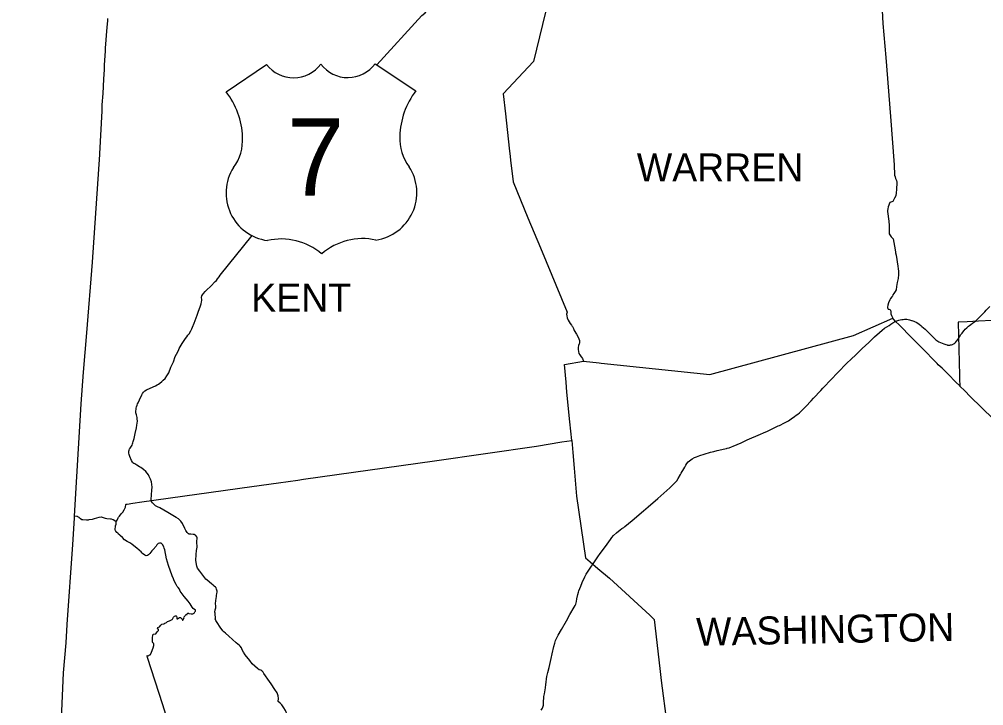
# Model space of a CAD drawing. Extents: x 0 to 2603, y -226 to 830.
# Drawn here: x 54.18 to 100.65, y 607.68 to 640.75 of the extents above; entities that cross this region are included whole.
import ezdxf

# ---------------------------------------------------------------- set-up
doc = ezdxf.new("R2010")
doc.units = 0
for name, color, linetype in [('CT_TSH_Map_Town_Limits', 7, 'Continuous'), ('CT_TSH_Map_Town_Text', 7, 'Continuous'), ('CT_TSH_Map_US_and_State_Routes', 7, 'Continuous')]:
    doc.layers.add(name, color=color, linetype=linetype)

msp = doc.modelspace()

# ---------------------------------------------------------------- linework, layer by layer
at = {"layer": 'CT_TSH_Map_Town_Limits'}
for points in [[(80.1, 643.411), (79.534, 641.088), (78.955, 638.71), (77.491, 637.157), (77.606, 636.187)], [(95.751, 641.169), (95.796, 640.551), (95.937, 638.907), (96.162, 636.059), (96.342, 633.743), (96.355, 633.241), (96.377, 633.159), (96.402, 633.086), (96.443, 632.986), (96.463, 632.909), (96.46, 632.887), (96.444, 632.554), (96.427, 632.388), (96.408, 632.247), (96.352, 632.129), (96.27, 631.97), (96.12, 631.921), (96.054, 631.705), (96.036, 631.609), (96.014, 631.534), (96.019, 631.485), (96.077, 631.022), (96.096, 630.809), (96.095, 630.53), (96.102, 630.489), (96.099, 630.416), (96.192, 630.266), (96.284, 630.179), (96.344, 629.81), (96.397, 629.545), (96.398, 629.494), (96.424, 629.385), (96.508, 628.847), (96.532, 628.726), (96.545, 628.614), (96.54, 628.459), (96.52, 628.263), (96.479, 628.072), (96.455, 627.868), (96.429, 627.708), (96.384, 627.626), (96.327, 627.532), (96.279, 627.466), (96.253, 627.403), (96.218, 627.372), (96.162, 627.297), (96.125, 627.234), (96.069, 627.092), (96.03, 626.969), (96.014, 626.875), (96.015, 626.842), (96.049, 626.79), (96.085, 626.782), (96.126, 626.76), (96.154, 626.734), (96.176, 626.655), (96.17, 626.609), (96.179, 626.557), (96.212, 626.47), (96.236, 626.419), (96.264, 626.347)], [(58.436, 640.783), (58.423, 640.667), (58.404, 640.363), (58.322, 639.354), (58.318, 639.232), (58.276, 638.538), (58.267, 638.336), (58.236, 637.859), (58.2, 637.17), (58.164, 636.633), (58.158, 636.346), (58.04, 634.269), (58.049, 634.232), (57.685, 629.053), (57.412, 625.648), (57.26, 623.755), (57.139, 622.216), (56.889, 617.899), (56.827, 616.808)], [(77.606, 636.187), (77.791, 634.532), (77.837, 634.146), (77.851, 633.965), (77.97, 632.916), (78.687, 631.189), (79.299, 629.735), (80.584, 626.632), (80.56, 626.594), (80.552, 626.544), (80.558, 626.464), (80.578, 626.369), (80.626, 626.253), (80.731, 626.091), (80.79, 626.019), (80.808, 625.983), (80.832, 625.948), (80.881, 625.85), (80.923, 625.757), (81.035, 625.586), (81.096, 625.47), (81.145, 625.352), (81.168, 625.279), (81.172, 625.143), (81.165, 625.107), (81.129, 625.026), (81.105, 624.943), (81.109, 624.835), (81.119, 624.745), (81.147, 624.65), (81.185, 624.575), (81.256, 624.49), (81.276, 624.472), (81.322, 624.399), (81.372, 624.278)], [(123.082, 617.737), (122.957, 618.259), (121.992, 621.988), (120.401, 627.917), (118.766, 627.682), (117.516, 627.46), (112.802, 626.95), (109.976, 626.777), (106.508, 626.575), (104.157, 626.438), (104.117, 626.429), (103.372, 626.362), (103.176, 626.354), (101.954, 626.288), (101.061, 626.24), (100.398, 626.21), (99.854, 626.177), (99.416, 626.152), (99.483, 623.59), (99.489, 623.377), (99.497, 623.12), (99.5, 623.08)], [(81.372, 624.278), (82.128, 624.19), (82.219, 624.187), (87.456, 623.636), (94.378, 625.507), (96.264, 626.347)], [(99.5, 623.08), (99.48, 623.098), (99.325, 623.256), (98.917, 623.661), (98.772, 623.812), (98.643, 623.94), (98.463, 624.106), (98.404, 624.168), (98.212, 624.358), (97.842, 624.742), (97.208, 625.387), (96.558, 626.046), (96.422, 626.178), (96.319, 626.285), (96.264, 626.347)], [(80.796, 620.456), (80.701, 621.352), (80.566, 622.789), (80.534, 623.262), (80.458, 624.12), (81.372, 624.278)], [(101.957, 615.974), (102.069, 617.732), (102.222, 620.412), (100.003, 622.578), (99.738, 622.841), (99.5, 623.08)], [(58.848, 616.535), (58.859, 616.562), (58.891, 616.62), (58.943, 616.728), (58.961, 616.758), (59.012, 616.816), (59.086, 616.918), (59.165, 617.009), (59.227, 617.111), (59.276, 617.212), (59.294, 617.242), (59.319, 617.368), (59.329, 617.382), (59.372, 617.393), (59.654, 617.437), (60.092, 617.494), (65.379, 618.237), (66.663, 618.413), (67.598, 618.548), (67.871, 618.585), (74.191, 619.469), (79.094, 620.179), (80.33, 620.389), (80.796, 620.456)], [(80.796, 620.456), (80.848, 619.874), (80.911, 619.122), (80.967, 618.543), (81.013, 617.971), (81.031, 617.779), (81.465, 614.798), (81.68, 614.608), (82.055, 614.284), (82.614, 613.822), (84.555, 612.035), (84.765, 611.835), (85.042, 609.477), (85.111, 608.892), (85.384, 606.809), (85.491, 606.099), (85.7, 604.798), (85.811, 603.998), (86.203, 601.565), (86.464, 600.083), (86.508, 599.804)], [(56.827, 616.808), (56.825, 616.707), (56.751, 615.439), (56.478, 611.587), (56.42, 610.703), (56.299, 609.259), (56.195, 607.042), (56.149, 605.817), (56.136, 605.715), (56.079, 605.082), (55.938, 603.558), (55.794, 601.866), (55.531, 598.701), (55.425, 597.346), (55.216, 594.938), (55.115, 593.729), (54.937, 591.45), (54.867, 590.481), (54.787, 589.52), (54.68, 588.216), (54.554, 586.636), (54.317, 583.992), (54.288, 583.676), (54.18, 582.466)], [(58.848, 616.535), (58.778, 616.589), (58.707, 616.625), (58.621, 616.66), (58.581, 616.665), (58.401, 616.675), (58.333, 616.691), (58.193, 616.747), (58.148, 616.753), (58.124, 616.755), (58.013, 616.745), (57.788, 616.68), (57.684, 616.648), (57.537, 616.634), (57.491, 616.623), (57.414, 616.618), (57.248, 616.628), (57.194, 616.637), (57.129, 616.675), (57.089, 616.713), (57.061, 616.739), (57.004, 616.778), (56.987, 616.791), (56.946, 616.8), (56.827, 616.808)], [(62.663, 612.228), (62.671, 612.274), (62.563, 612.365), (62.504, 612.424), (62.418, 612.58), (62.317, 612.715), (62.124, 612.941), (61.932, 613.196), (61.904, 613.291), (61.837, 613.374), (61.788, 613.425), (61.731, 613.516), (61.643, 613.691), (61.606, 613.791), (61.54, 613.929), (61.363, 614.425), (61.28, 614.757), (61.194, 615.191), (61.168, 615.273), (61.141, 615.336), (61.079, 615.437), (61.046, 615.478), (61.009, 615.51), (60.982, 615.515), (60.935, 615.509), (60.868, 615.488), (60.812, 615.429), (60.768, 615.363), (60.634, 615.197), (60.573, 615.134), (60.463, 615.007), (60.406, 614.948), (60.363, 614.913), (60.293, 614.906), (60.23, 614.927), (60.11, 615.016), (60.072, 615.048), (60.063, 615.075), (59.847, 615.265), (59.783, 615.313), (59.595, 615.467), (59.506, 615.525), (59.384, 615.588), (59.255, 615.672), (59.149, 615.776), (59.053, 615.857), (59.025, 615.896), (58.946, 615.965), (58.923, 615.988), (58.882, 616.018), (58.832, 616.082), (58.817, 616.107), (58.8, 616.169), (58.8, 616.197), (58.817, 616.3), (58.823, 616.35), (58.842, 616.43), (58.848, 616.535)], [(61.316, 606.997), (61.09, 607.721), (60.358, 609.995), (60.338, 610.081), (60.341, 610.093), (60.417, 610.079), (60.422, 610.089), (60.459, 610.121), (60.484, 610.128), (60.503, 610.141), (60.523, 610.174), (60.545, 610.262), (60.634, 610.471), (60.659, 610.585), (60.666, 610.66), (60.647, 610.686), (60.613, 610.709), (60.597, 610.734), (60.6, 610.936), (60.616, 611.085), (60.634, 611.112), (60.651, 611.12), (60.756, 611.146), (60.83, 611.231), (60.884, 611.306), (60.888, 611.351), (60.847, 611.421), (60.862, 611.447), (60.941, 611.483), (61.003, 611.564), (61.051, 611.609), (61.141, 611.629), (61.196, 611.647), (61.271, 611.686), (61.324, 611.733), (61.41, 611.759), (61.54, 611.826), (61.564, 611.852), (61.61, 611.94), (61.66, 611.991), (61.711, 612.008), (61.736, 612), (61.752, 611.984), (61.768, 611.934), (61.768, 611.888), (61.773, 611.866), (61.791, 611.859), (61.809, 611.87), (61.845, 611.902), (61.898, 611.919), (61.941, 611.924), (61.996, 611.886), (62.019, 611.877), (62.033, 611.851), (62.048, 611.804), (62.058, 611.8), (62.066, 611.804), (62.12, 611.904), (62.116, 611.949), (62.119, 611.966), (62.15, 611.99), (62.17, 612.025), (62.213, 612.071), (62.256, 612.069), (62.272, 612.077), (62.285, 612.128), (62.303, 612.134), (62.335, 612.128), (62.348, 612.122), (62.465, 612.098), (62.51, 612.097), (62.537, 612.104), (62.603, 612.141), (62.632, 612.201), (62.663, 612.228)]]:
    msp.add_lwpolyline(points, dxfattribs=at)
at = {"layer": 'CT_TSH_Map_US_and_State_Routes'}
for p, q in [((64.143, 637.259), (66.096, 638.575)), ((71.329, 638.606), (73.292, 637.301)), ((64.143, 637.261), (64.143, 637.259)), ((96.088, 626), (96.174, 626.06)), ((100.033, 626.049), (100.116, 626.102)), ((98.562, 625.184), (98.729, 625.115)), ((94.693, 624.786), (94.797, 624.884)), ((94.046, 624.169), (94.279, 624.388)), ((92.903, 622.979), (92.963, 623.042)), ((91.689, 621.727), (91.767, 621.795)), ((91.368, 621.501), (91.534, 621.614)), ((91.534, 621.614), (91.61, 621.67)), ((91.61, 621.67), (91.689, 621.727)), ((89.788, 620.712), (90.146, 620.869)), ((90.146, 620.869), (90.199, 620.895)), ((87.646, 619.931), (87.799, 619.969)), ((87.799, 619.969), (88.183, 620.053)), ((88.183, 620.053), (88.257, 620.073)), ((88.257, 620.073), (88.283, 620.079)), ((88.283, 620.079), (88.383, 620.106)), ((88.383, 620.106), (88.501, 620.155)), ((88.501, 620.155), (88.575, 620.185)), ((86.203, 619.083), (86.245, 619.164)), ((85.523, 618.168), (85.859, 618.516)), ((83.36, 616.318), (83.707, 616.599)), ((82.659, 615.678), (82.697, 615.736)), ((82.697, 615.736), (82.739, 615.789)), ((82.739, 615.789), (82.815, 615.873)), ((82.171, 615.015), (82.423, 615.352)), ((82.423, 615.352), (82.659, 615.678)), ((82.058, 614.851), (82.171, 615.015)), ((81.304, 613.614), (81.428, 613.879)), ((81.149, 613.214), (81.232, 613.438)), ((81.232, 613.438), (81.304, 613.614)), ((80.715, 612.064), (80.922, 612.419)), ((79.937, 610.528), (79.98, 610.691)), ((79.555, 608.702), (79.566, 608.815))]:
    msp.add_line(p, q, dxfattribs=at)
for points in [[(71.406, 638.555), (73.584, 640.927), (73.638, 640.982), (73.741, 641.068), (73.806, 641.133), (73.875, 641.199), (73.94, 641.25), (74.064, 641.329)], [(62.604, 626.11), (62.748, 626.489), (62.799, 626.642), (62.907, 626.938), (62.945, 627.044), (62.964, 627.128), (62.976, 627.201), (62.976, 627.252), (62.967, 627.342), (62.975, 627.42), (63, 627.475), (63.06, 627.544), (63.139, 627.626), (63.208, 627.695), (63.403, 627.889), (63.619, 628.111), (63.677, 628.17), (63.734, 628.239), (63.809, 628.347), (63.856, 628.414), (65.394, 630.324)], [(100.483, 626.433), (100.7, 626.655), (100.768, 626.727), (100.952, 626.916)], [(100.116, 626.102), (100.249, 626.208), (100.357, 626.303), (100.483, 626.433)], [(62.529, 625.913), (62.604, 626.11)], [(95.254, 625.318), (95.39, 625.448), (95.633, 625.658), (95.76, 625.772), (95.87, 625.867), (96.088, 626)], [(96.174, 626.06), (96.267, 626.124), (96.413, 626.197), (96.511, 626.232), (96.553, 626.245)], [(96.553, 626.245), (96.621, 626.263), (96.701, 626.279), (96.767, 626.291), (96.835, 626.3), (96.895, 626.305)], [(96.895, 626.305), (96.915, 626.308), (96.944, 626.302)], [(96.944, 626.302), (97.012, 626.288), (97.072, 626.272), (97.165, 626.244), (97.18, 626.239)], [(97.18, 626.239), (97.236, 626.219), (97.282, 626.202), (97.347, 626.175), (97.39, 626.151)], [(97.39, 626.151), (97.42, 626.138), (97.535, 626.057), (97.623, 625.992), (97.675, 625.954), (97.75, 625.885)], [(99.831, 625.886), (99.888, 625.938), (99.924, 625.971), (99.963, 626.003), (100.033, 626.049)], [(62.033, 625.128), (62.095, 625.223), (62.186, 625.369), (62.252, 625.456), (62.308, 625.528), (62.363, 625.601), (62.447, 625.736)], [(62.447, 625.736), (62.498, 625.839), (62.529, 625.913)], [(97.75, 625.885), (97.822, 625.822), (98.049, 625.599), (98.153, 625.492), (98.285, 625.366), (98.345, 625.308), (98.399, 625.265), (98.489, 625.213), (98.562, 625.184)], [(99.177, 625.099), (99.201, 625.108), (99.235, 625.135), (99.283, 625.178), (99.345, 625.245), (99.413, 625.333), (99.454, 625.393), (99.49, 625.456), (99.555, 625.557), (99.604, 625.624), (99.645, 625.677), (99.715, 625.761), (99.764, 625.816), (99.831, 625.886)], [(61.929, 624.964), (62.033, 625.128)], [(94.797, 624.884), (95.11, 625.181), (95.254, 625.318)], [(98.729, 625.115), (98.771, 625.092), (98.829, 625.074), (98.884, 625.059), (98.909, 625.056), (98.944, 625.051), (99.013, 625.056), (99.052, 625.061)], [(99.052, 625.061), (99.096, 625.069), (99.139, 625.081), (99.177, 625.099)], [(61.049, 623.291), (61.115, 623.357), (61.202, 623.45), (61.295, 623.568), (61.379, 623.718), (61.48, 623.981), (61.534, 624.085), (61.604, 624.253), (61.695, 624.501), (61.759, 624.621), (61.854, 624.791), (61.889, 624.886), (61.929, 624.964)], [(94.279, 624.388), (94.47, 624.572), (94.564, 624.664), (94.693, 624.786)], [(93.526, 623.629), (93.768, 623.881), (93.909, 624.03), (94.046, 624.169)], [(92.963, 623.042), (93.266, 623.358), (93.377, 623.477), (93.526, 623.629)], [(60.74, 623.09), (60.823, 623.129), (60.892, 623.166), (60.951, 623.211), (61.049, 623.291)], [(60.091, 622.654), (60.124, 622.724), (60.173, 622.791), (60.23, 622.85), (60.308, 622.901), (60.481, 622.977), (60.74, 623.09)], [(92.45, 622.488), (92.806, 622.87), (92.903, 622.979)], [(59.801, 621.853), (59.801, 621.887), (59.804, 621.952), (59.814, 622.019), (59.829, 622.079), (59.852, 622.154), (59.878, 622.214), (59.905, 622.272)], [(59.905, 622.272), (59.971, 622.41)], [(59.971, 622.41), (60.091, 622.654)], [(91.767, 621.795), (91.896, 621.913), (92.078, 622.097), (92.342, 622.366), (92.45, 622.488)], [(59.823, 621.069), (59.847, 621.197), (59.859, 621.292), (59.868, 621.384), (59.862, 621.493), (59.852, 621.563), (59.821, 621.69), (59.811, 621.736), (59.803, 621.792), (59.801, 621.853)], [(90.622, 621.103), (90.749, 621.154), (90.81, 621.179), (91.059, 621.307)], [(91.059, 621.307), (91.236, 621.403), (91.368, 621.501)], [(59.765, 620.785), (59.823, 621.069)], [(90.199, 620.895), (90.461, 621.023), (90.622, 621.103)], [(59.505, 619.677), (59.485, 619.727), (59.468, 619.786), (59.46, 619.841), (59.459, 619.894), (59.466, 619.945), (59.477, 619.996), (59.498, 620.048), (59.525, 620.089), (59.555, 620.131), (59.584, 620.177), (59.611, 620.226), (59.636, 620.287), (59.651, 620.34), (59.672, 620.414), (59.708, 620.547), (59.748, 620.717), (59.765, 620.785)], [(88.575, 620.185), (88.957, 620.342), (89.089, 620.406), (89.247, 620.485), (89.363, 620.542), (89.788, 620.712)], [(86.535, 619.529), (86.604, 619.576), (86.71, 619.633), (86.814, 619.672), (86.967, 619.725), (87.186, 619.801), (87.479, 619.885), (87.646, 619.931)], [(60.578, 618.203), (60.569, 618.34), (60.546, 618.463), (60.502, 618.592), (60.446, 618.717), (60.404, 618.795), (60.345, 618.879), (60.27, 618.965), (60.168, 619.061), (60.041, 619.152), (59.977, 619.193), (59.846, 619.271), (59.74, 619.326), (59.696, 619.345), (59.654, 619.373), (59.627, 619.407), (59.591, 619.49), (59.505, 619.677)], [(86.417, 619.42), (86.478, 619.48), (86.535, 619.529)], [(85.859, 618.516), (85.921, 618.626), (86.044, 618.813), (86.079, 618.876), (86.203, 619.083)], [(86.245, 619.164), (86.304, 619.261), (86.352, 619.34), (86.417, 619.42)], [(62.33, 615.966), (62.265, 616.028), (62.21, 616.112), (62.152, 616.219), (62.048, 616.462), (61.961, 616.569), (61.857, 616.673), (61.731, 616.751), (61.34, 616.985), (60.959, 617.207), (60.837, 617.257), (60.749, 617.312), (60.667, 617.381), (60.594, 617.448), (60.551, 617.523), (60.531, 617.608), (60.574, 618.064), (60.578, 618.203)], [(84.487, 617.263), (84.947, 617.655), (85.523, 618.168)], [(83.707, 616.599), (84.256, 617.064), (84.487, 617.263)], [(82.815, 615.873), (82.955, 616.012), (83.133, 616.155), (83.213, 616.211)], [(83.213, 616.211), (83.305, 616.266), (83.36, 616.318)], [(62.552, 615.932), (62.451, 615.943), (62.384, 615.94), (62.366, 615.944), (62.345, 615.953), (62.33, 615.966)], [(63.449, 613.541), (63.226, 613.719), (63.166, 613.771), (62.881, 614.158), (62.774, 614.302), (62.733, 614.401), (62.692, 614.677), (62.707, 614.956), (62.721, 615.16), (62.75, 615.31), (62.742, 615.575), (62.747, 615.761), (62.728, 615.814), (62.683, 615.873), (62.652, 615.9), (62.604, 615.922), (62.552, 615.932)], [(81.428, 613.879), (81.498, 614.007), (82.058, 614.851)], [(63.659, 613.349), (63.627, 613.394), (63.572, 613.444), (63.518, 613.485), (63.449, 613.541)], [(63.658, 612.744), (63.68, 612.945)], [(63.692, 613.071), (63.708, 613.161), (63.708, 613.202), (63.703, 613.245), (63.69, 613.29), (63.659, 613.349)], [(63.68, 612.945), (63.689, 613.008)], [(63.689, 613.008), (63.692, 613.071)], [(81.049, 612.827), (81.096, 613.039), (81.129, 613.142), (81.149, 613.214)], [(63.627, 611.861), (63.612, 612.134), (63.604, 612.185), (63.625, 612.298), (63.644, 612.394), (63.649, 612.493), (63.642, 612.587), (63.658, 612.744)], [(80.922, 612.419), (80.962, 612.498), (80.992, 612.573), (81.026, 612.696), (81.049, 612.827)], [(80.149, 611.075), (80.307, 611.353), (80.543, 611.77), (80.715, 612.064)], [(64.785, 610.578), (64.623, 610.708), (64.277, 611.035), (64.114, 611.177), (64.04, 611.24), (63.987, 611.29), (63.864, 611.465), (63.71, 611.691), (63.649, 611.787), (63.625, 611.865)], [(79.98, 610.691), (80.022, 610.812), (80.083, 610.953), (80.149, 611.075)], [(65.395, 609.7), (65.29, 609.849), (65.065, 610.134), (64.985, 610.252), (64.922, 610.362), (64.884, 610.461), (64.829, 610.539), (64.785, 610.578)], [(79.652, 609.283), (79.719, 609.513), (79.809, 609.945), (79.864, 610.178), (79.937, 610.528)], [(66.661, 607.885), (66.666, 608.024), (66.647, 608.157), (66.602, 608.29), (66.498, 608.458), (66.323, 608.735), (66.152, 608.949), (66.046, 609.114), (65.966, 609.228), (65.936, 609.292), (65.859, 609.359), (65.817, 609.384), (65.739, 609.411), (65.654, 609.468), (65.525, 609.579), (65.395, 609.7)], [(79.566, 608.815), (79.582, 608.977), (79.603, 609.079), (79.652, 609.283)], [(79.334, 607.469), (79.39, 607.565), (79.432, 607.709), (79.444, 607.793), (79.444, 607.884), (79.454, 608.061), (79.46, 608.121), (79.487, 608.244), (79.538, 608.542), (79.555, 608.702)], [(67.085, 607.247), (67.007, 607.44), (66.931, 607.58), (66.831, 607.72), (66.755, 607.803), (66.661, 607.885)]]:
    msp.add_lwpolyline(points, dxfattribs=at)
for centre, radius, start, end in [((67.397, 639.561), 1.632, 217.1377, 323.3979), ((70.014, 639.573), 1.632, 217.1377, 323.3979), ((61.216, 634.962), 3.722, 1.8086, 38.1428), ((76.237, 635.033), 3.722, 142.3929, 178.7271), ((62.709, 634.939), 2.232, 323.1742, 3.6193), ((74.745, 634.995), 2.232, 176.9164, 217.3614), ((66.451, 632.376), 2.308, 147.9382, 262.1377), ((71.027, 632.397), 2.308, 278.3979, 32.5975), ((66.802, 627.155), 3.009, 49.6665, 102.7966), ((70.725, 627.173), 3.009, 77.739, 130.8691)]:
    msp.add_arc(centre, radius, start, end, dxfattribs=at)

# ---------------------------------------------------------------- texts
at = {"layer": 'CT_TSH_Map_Town_Text'}
for s, p in [('WARREN', (83.936, 632.936)), ('KENT', (65.357, 626.66))]:
    msp.add_text(s, height=1.35, dxfattribs=at).set_placement(p)
msp.add_text('WASHINGTON', height=1.35, rotation=1.1384, dxfattribs=at).set_placement((86.808, 610.558))
at = {"layer": 'CT_TSH_Map_US_and_State_Routes'}
msp.add_text('7', height=3.714, dxfattribs=at).set_placement((67.079, 632.259))

doc.saveas('drawing.dxf')
